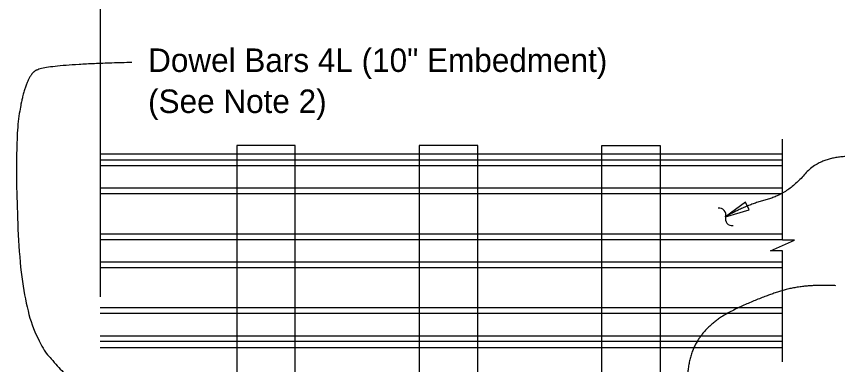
# Model space of a CAD drawing. Extents: x 1.5 to 68.7, y 0 to 31.
# Drawn here: x 5.82 to 12.85, y 13.32 to 16.3 of the extents above; entities that cross this region are included whole.
import ezdxf

# ---------------------------------------------------------------- set-up
doc = ezdxf.new("R2010")
doc.units = 0
doc.layers.add('AdhocPoint_dp', color=7, linetype='Continuous')
doc.layers.add('Patterning', color=7, linetype='Continuous')

msp = doc.modelspace()

# ---------------------------------------------------------------- linework, layer by layer
at = {"layer": 'AdhocPoint_dp'}
msp.add_lwpolyline([(12.3808, 13.3413), (12.3808, 14.2947), (12.2775, 14.2947), (12.3808, 14.3397), (12.4842, 14.3847), (12.3808, 14.3847), (12.3808, 15.2514)], dxfattribs=at)
msp.add_lwpolyline([(11.893, 14.5864), (12.0953, 14.6471), (12.0641, 14.7103)], close=True, dxfattribs=at)
for centre, start, end in [((11.8359, 14.602), 344.25937, 95.98659), ((11.9507, 14.5696), 164.25937, 275.98659)]:
    msp.add_arc(centre, 0.0596, start, end, dxfattribs=at)
for points in [[(6.8093, 15.9088), (6.0612, 15.8929), (5.9024, 15.7817), (5.8017, 15.236), (5.8706, 13.668), (6.3154, 13.1303), (6.7761, 12.8283), (7.0775, 12.6089)], [(12.9919, 15.1029), (12.706, 15.1121), (12.429, 14.7831), (12.0627, 14.6848), (11.8929, 14.5864)], [(12.837, 13.9956), (12.5596, 14.0093), (12.1826, 13.8927), (11.762, 13.6895), (11.5665, 13.3921), (11.5665, 12.9582), (11.0189, 12.8991), (10.5496, 12.8912)]]:
    msp.add_open_spline(points, degree=2, dxfattribs=at)
at = {"layer": 'Patterning'}
for p, q in [((6.5373, 21.2192), (6.5373, 13.8998)), ((6.5374, 15.1264), (12.3833, 15.1264)), ((6.5374, 15.0742), (12.3833, 15.0742)), ((6.5374, 15.026), (12.3833, 15.026)), ((6.5374, 14.8332), (12.3833, 14.8332)), ((6.5374, 14.7849), (12.3833, 14.7849)), ((6.5374, 14.441), (12.3833, 14.441)), ((6.5374, 14.3928), (12.3833, 14.3928)), ((6.5374, 14.1999), (12.3833, 14.1999)), ((6.5374, 14.1518), (12.3833, 14.1518)), ((6.5374, 13.8079), (12.3833, 13.8079)), ((6.5374, 13.7596), (12.3833, 13.7596)), ((6.5374, 13.5668), (12.3833, 13.5668)), ((6.5374, 13.5186), (12.3833, 13.5186)), ((6.5374, 13.4663), (12.3833, 13.4663))]:
    msp.add_line(p, q, dxfattribs=at)
for points in [[(8.2082, 11.3761), (8.2082, 15.1963), (7.7082, 15.1963), (7.7082, 11.3761)], [(9.7707, 11.3761), (9.7707, 15.1963), (9.2707, 15.1963), (9.2707, 11.3761)], [(10.8332, 11.3761), (10.8332, 15.1963), (11.3332, 15.1963), (11.3332, 11.3761)]]:
    msp.add_lwpolyline(points, dxfattribs=at)

# ---------------------------------------------------------------- texts
at = {"layer": 'AdhocPoint_dp'}
for s, p in [('Dowel Bars 4L (10" Embedment) ', (6.9491, 15.8279)), ('(See Note 2)', (6.9491, 15.4759))]:
    msp.add_text(s, height=0.2016, dxfattribs=at).set_placement(p)

doc.saveas('drawing.dxf')
